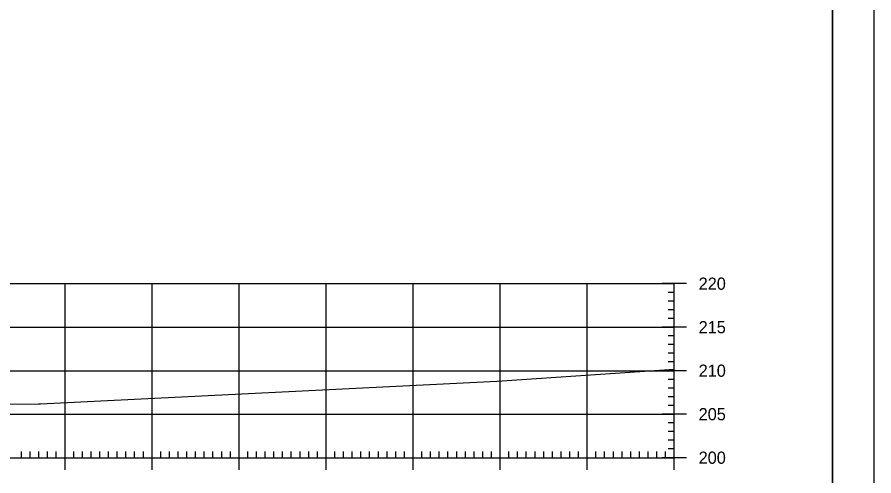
# Model space of a CAD drawing. Extents: x 1312042 to 1371461, y 379929 to 1834241.
# Drawn here: x 1371362.8 to 1371461.2, y 380250.2 to 380302.9 of the extents above; entities that cross this region are included whole.
import ezdxf

# ---------------------------------------------------------------- set-up
doc = ezdxf.new("R2010")
doc.units = 0
for name, color, linetype in [('R_Axis', 7, 'Continuous'), ('R_Axis Annot', 7, 'Continuous'), ('R_Border', 7, 'Continuous'), ('R_Exist Surface', 7, 'Continuous'), ('R_Grid', 7, 'Continuous'), ('R_No Plot', 7, 'Continuous')]:
    doc.layers.add(name, color=color, linetype=linetype)

msp = doc.modelspace()

# ---------------------------------------------------------------- linework, layer by layer
at = {"layer": 'R_Axis'}
for p, q in [((1371439.677, 380272.247), (1371436.877, 380272.247)), ((1371438.277, 380252.247), (1371438.277, 380272.247)), ((1371438.277, 380271.247), (1371437.577, 380271.247)), ((1371438.277, 380270.247), (1371437.577, 380270.247)), ((1371438.277, 380269.247), (1371437.577, 380269.247)), ((1371438.277, 380268.247), (1371437.577, 380268.247)), ((1371439.677, 380267.247), (1371436.877, 380267.247)), ((1371438.277, 380266.247), (1371437.577, 380266.247)), ((1371438.277, 380265.247), (1371437.577, 380265.247)), ((1371438.277, 380264.247), (1371437.577, 380264.247)), ((1371438.277, 380263.247), (1371437.577, 380263.247)), ((1371439.677, 380262.247), (1371436.877, 380262.247)), ((1371438.277, 380261.247), (1371437.577, 380261.247)), ((1371438.277, 380260.247), (1371437.577, 380260.247)), ((1371438.277, 380259.247), (1371437.577, 380259.247)), ((1371438.277, 380258.247), (1371437.577, 380258.247)), ((1371439.677, 380257.247), (1371436.877, 380257.247)), ((1371438.277, 380256.247), (1371437.577, 380256.247)), ((1371438.277, 380255.247), (1371437.577, 380255.247)), ((1371438.277, 380254.247), (1371437.577, 380254.247)), ((1371363.277, 380252.247), (1371363.277, 380252.947)), ((1371364.277, 380252.247), (1371364.277, 380252.947)), ((1371365.277, 380252.247), (1371365.277, 380252.947)), ((1371366.277, 380252.247), (1371366.277, 380252.947)), ((1371367.277, 380252.247), (1371367.277, 380252.947)), ((1371368.277, 380250.847), (1371368.277, 380253.647)), ((1371369.277, 380252.247), (1371369.277, 380252.947)), ((1371370.277, 380252.247), (1371370.277, 380252.947)), ((1371371.277, 380252.247), (1371371.277, 380252.947)), ((1371372.277, 380252.247), (1371372.277, 380252.947)), ((1371373.277, 380252.247), (1371373.277, 380252.947)), ((1371374.277, 380252.247), (1371374.277, 380252.947)), ((1371375.277, 380252.247), (1371375.277, 380252.947)), ((1371376.277, 380252.247), (1371376.277, 380252.947)), ((1371377.277, 380252.247), (1371377.277, 380252.947)), ((1371378.277, 380250.847), (1371378.277, 380253.647)), ((1371379.277, 380252.247), (1371379.277, 380252.947)), ((1371380.277, 380252.247), (1371380.277, 380252.947)), ((1371381.277, 380252.247), (1371381.277, 380252.947)), ((1371382.277, 380252.247), (1371382.277, 380252.947)), ((1371383.277, 380252.247), (1371383.277, 380252.947)), ((1371384.277, 380252.247), (1371384.277, 380252.947)), ((1371385.277, 380252.247), (1371385.277, 380252.947)), ((1371386.277, 380252.247), (1371386.277, 380252.947)), ((1371387.277, 380252.247), (1371387.277, 380252.947)), ((1371388.277, 380250.847), (1371388.277, 380253.647)), ((1371389.277, 380252.247), (1371389.277, 380252.947)), ((1371390.277, 380252.247), (1371390.277, 380252.947)), ((1371391.277, 380252.247), (1371391.277, 380252.947)), ((1371392.277, 380252.247), (1371392.277, 380252.947)), ((1371393.277, 380252.247), (1371393.277, 380252.947)), ((1371394.277, 380252.247), (1371394.277, 380252.947)), ((1371395.277, 380252.247), (1371395.277, 380252.947)), ((1371396.277, 380252.247), (1371396.277, 380252.947)), ((1371397.277, 380252.247), (1371397.277, 380252.947)), ((1371398.277, 380250.847), (1371398.277, 380253.647)), ((1371399.277, 380252.247), (1371399.277, 380252.947)), ((1371400.277, 380252.247), (1371400.277, 380252.947)), ((1371401.277, 380252.247), (1371401.277, 380252.947)), ((1371402.277, 380252.247), (1371402.277, 380252.947)), ((1371403.277, 380252.247), (1371403.277, 380252.947)), ((1371404.277, 380252.247), (1371404.277, 380252.947)), ((1371405.277, 380252.247), (1371405.277, 380252.947)), ((1371406.277, 380252.247), (1371406.277, 380252.947)), ((1371407.277, 380252.247), (1371407.277, 380252.947)), ((1371408.277, 380250.847), (1371408.277, 380253.647)), ((1371409.277, 380252.247), (1371409.277, 380252.947)), ((1371410.277, 380252.247), (1371410.277, 380252.947)), ((1371411.277, 380252.247), (1371411.277, 380252.947)), ((1371412.277, 380252.247), (1371412.277, 380252.947)), ((1371413.277, 380252.247), (1371413.277, 380252.947)), ((1371414.277, 380252.247), (1371414.277, 380252.947)), ((1371415.277, 380252.247), (1371415.277, 380252.947)), ((1371416.277, 380252.247), (1371416.277, 380252.947)), ((1371417.277, 380252.247), (1371417.277, 380252.947)), ((1371418.277, 380250.847), (1371418.277, 380253.647)), ((1371419.277, 380252.247), (1371419.277, 380252.947)), ((1371420.277, 380252.247), (1371420.277, 380252.947)), ((1371421.277, 380252.247), (1371421.277, 380252.947)), ((1371422.277, 380252.247), (1371422.277, 380252.947)), ((1371423.277, 380252.247), (1371423.277, 380252.947)), ((1371424.277, 380252.247), (1371424.277, 380252.947)), ((1371425.277, 380252.247), (1371425.277, 380252.947)), ((1371426.277, 380252.247), (1371426.277, 380252.947)), ((1371427.277, 380252.247), (1371427.277, 380252.947)), ((1371428.277, 380250.847), (1371428.277, 380253.647)), ((1371429.277, 380252.247), (1371429.277, 380252.947)), ((1371430.277, 380252.247), (1371430.277, 380252.947)), ((1371431.277, 380252.247), (1371431.277, 380252.947)), ((1371432.277, 380252.247), (1371432.277, 380252.947)), ((1371433.277, 380252.247), (1371433.277, 380252.947)), ((1371434.277, 380252.247), (1371434.277, 380252.947)), ((1371435.277, 380252.247), (1371435.277, 380252.947)), ((1371436.277, 380252.247), (1371436.277, 380252.947)), ((1371437.277, 380252.247), (1371437.277, 380252.947)), ((1371438.277, 380253.247), (1371437.577, 380253.247)), ((1371438.277, 380250.847), (1371438.277, 380253.647)), ((1371158.277, 380252.247), (1371438.277, 380252.247)), ((1371439.677, 380252.247), (1371436.877, 380252.247))]:
    msp.add_line(p, q, dxfattribs=at)
at = {"layer": 'R_Border'}
msp.add_line((1371456.457, 380146.247), (1371456.457, 380351.707), dxfattribs=at)
at = {"layer": 'R_Exist Surface'}
msp.add_lwpolyline([(1371350.738, 380258.351), (1371365.236, 380258.45), (1371365.447, 380258.451), (1371417.893, 380261.048), (1371417.926, 380261.051), (1371438.277, 380262.42)], dxfattribs=at)
at = {"layer": 'R_Grid'}
for p, q in [((1371158.277, 380272.247), (1371438.277, 380272.247)), ((1371368.277, 380252.247), (1371368.277, 380272.247)), ((1371378.277, 380252.247), (1371378.277, 380272.247)), ((1371388.277, 380252.247), (1371388.277, 380272.247)), ((1371398.277, 380252.247), (1371398.277, 380272.247)), ((1371408.277, 380252.247), (1371408.277, 380272.247)), ((1371418.277, 380252.247), (1371418.277, 380272.247)), ((1371428.277, 380252.247), (1371428.277, 380272.247)), ((1371438.277, 380252.247), (1371438.277, 380272.247)), ((1371158.277, 380267.247), (1371438.277, 380267.247)), ((1371158.277, 380262.247), (1371438.277, 380262.247)), ((1371158.277, 380257.247), (1371438.277, 380257.247)), ((1371158.277, 380252.247), (1371438.277, 380252.247))]:
    msp.add_line(p, q, dxfattribs=at)
at = {"layer": 'R_No Plot'}
for points in [[(1371127.869, 380355.601), (1371461.209, 380355.601), (1371461.209, 380142.264), (1371127.869, 380142.264)], [(1371374.197, 380351.707), (1371374.197, 380341.827), (1371409.929, 380341.827), (1371409.929, 380338.907), (1371433.128, 380338.907), (1371433.128, 380314.574), (1371456.457, 380314.574), (1371456.457, 380146.247), (1371140.277, 380146.247), (1371140.277, 380351.707)]]:
    msp.add_lwpolyline(points, close=True, dxfattribs=at)

# ---------------------------------------------------------------- texts
at = {"layer": 'R_Axis Annot'}
for s, p in [('220', (1371441.077, 380271.547)), ('215', (1371441.077, 380266.547)), ('210', (1371441.077, 380261.547)), ('205', (1371441.077, 380256.547)), ('200', (1371441.077, 380251.547))]:
    msp.add_text(s, height=1.4, dxfattribs=at).set_placement(p)

doc.saveas('drawing.dxf')
